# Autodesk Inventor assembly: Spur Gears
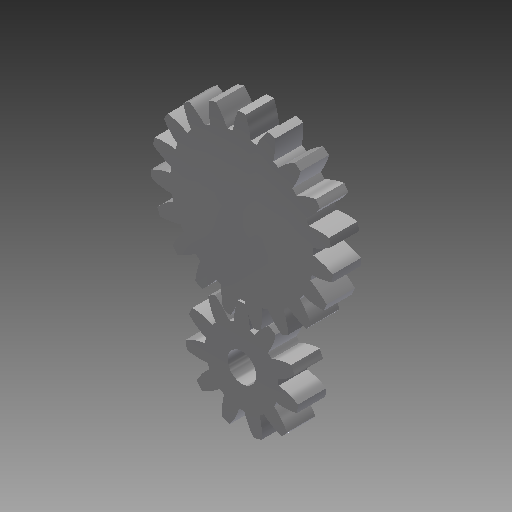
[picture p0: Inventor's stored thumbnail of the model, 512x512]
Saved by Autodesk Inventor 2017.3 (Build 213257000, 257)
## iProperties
Created: 2020-03
Part Number: Spur Gears
Document SubType Name: Assembly
Designer: Tim_G
Categories: <?xml version="1.0" encoding="UTF-16"?> <MemberInstance><Categories><FamilyTemplate/><ParamToTemplateMap><ParamToTemplate><ParamToTemplate CategoryParameter="//
ClientObjectVersion: 1
Author: Tim_G
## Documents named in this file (3)
- C:\Users\Tim_G\OneDrive - McMaster University\Documents\Documents\Books\McMaster First Year Courses\Winter Engineering 1C03\Project\Project Files (Prosthetic Frame Assembly)\Hand Assembly\Design Accelerator\Spur Gears5.iam
- C:\Users\Tim_G\OneDrive - McMaster University\Documents\Documents\Books\McMaster First Year Courses\Winter Engineering 1C03\Project\Project Files (Prosthetic Frame Assembly)\Hand Assembly\Design Accelerator\Spur Gear15.ipt
- C:\Users\Tim_G\OneDrive - McMaster University\Documents\Documents\Books\McMaster First Year Courses\Winter Engineering 1C03\Project\Project Files (Prosthetic Frame Assembly)\Hand Assembly\Design Accelerator\Spur Gear25.ipt
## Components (2 placed, 2 different names)
1. Spur Gear1:1 — Rotation:1
2. Spur Gear2:1 — Rotation:1
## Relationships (1: RelateRotation 1)
- Rotation:1 [RelateRotation]: Spur Gear1:1 ↔ Spur Gear2:1
